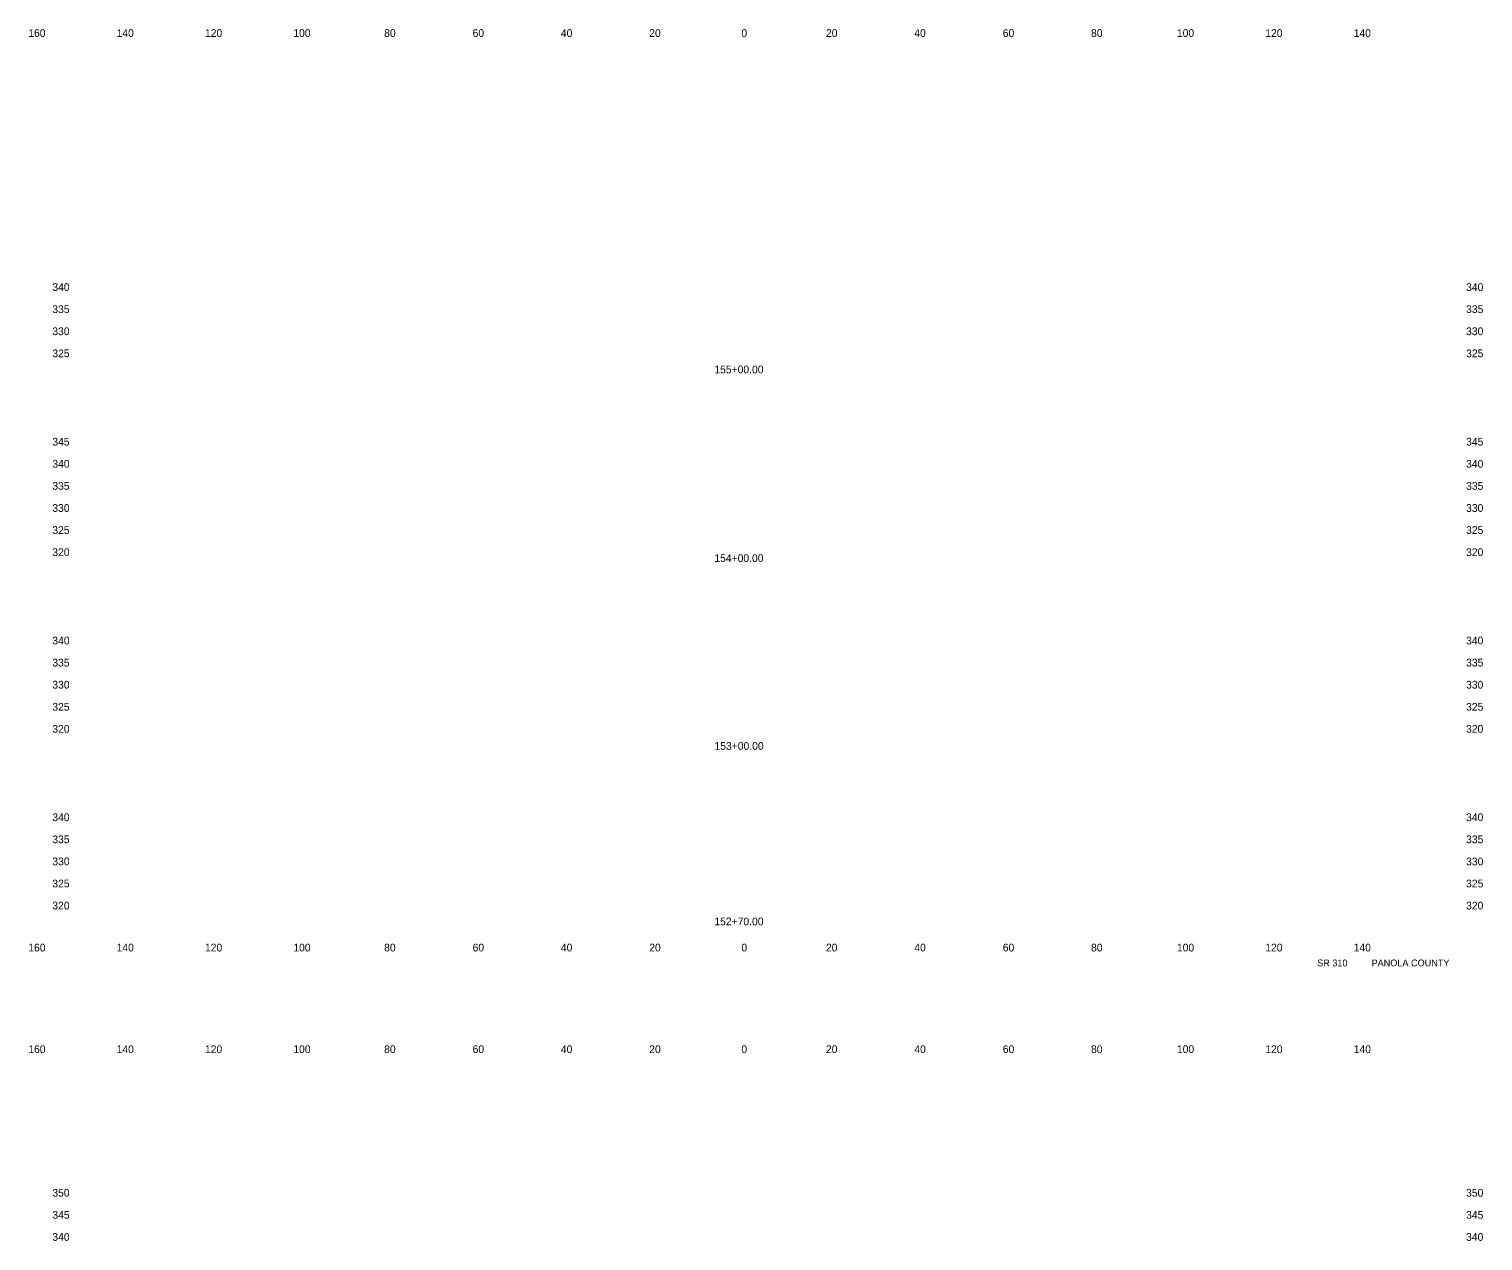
# Model space of a CAD drawing. Extents: x 21481 to 21810, y 6485 to 11067.
# Drawn here: x 21480.9 to 21809.9, y 10792.7 to 11067 of the extents above; entities that cross this region are included whole.
import ezdxf

# ---------------------------------------------------------------- set-up
doc = ezdxf.new("R2010")
doc.units = 0
for name, color, linetype in [('62', 7, 'Continuous'), ('XS_CELL', 7, 'Continuous'), ('XS_P_TX_DCH', 7, 'Continuous'), ('XS_P_TX_FS_BS', 7, 'Continuous')]:
    doc.layers.add(name, color=color, linetype=linetype)

msp = doc.modelspace()

# ---------------------------------------------------------------- texts
at = {"layer": '62'}
for s, p in [('  160  ', (21479.4, 11065.21)), ('  140  ', (21499.39, 11065.21)), ('  120  ', (21519.39, 11065.21)), ('  100  ', (21539.39, 11065.21)), ('  80  ', (21559.95, 11065.21)), ('  60  ', (21579.97, 11065.21)), ('  40  ', (21599.95, 11065.21)), ('  20  ', (21619.95, 11065.21)), ('  0  ', (21640.81, 11065.21)), ('  0  ', (21640.81, 11065.21)), ('  20  ', (21659.95, 11065.21)), ('  40  ', (21679.95, 11065.21)), ('  60  ', (21699.97, 11065.21)), ('  80  ', (21719.95, 11065.21)), ('  100  ', (21739.39, 11065.21)), ('  120  ', (21759.39, 11065.21)), ('  140  ', (21779.39, 11065.21)), ('  160  ', (21479.4, 10858.21)), ('  140  ', (21499.39, 10858.21)), ('  120  ', (21519.39, 10858.21)), ('  100  ', (21539.39, 10858.21)), ('  80  ', (21559.95, 10858.21)), ('  60  ', (21579.97, 10858.21)), ('  40  ', (21599.95, 10858.21)), ('  20  ', (21619.95, 10858.21)), ('  0  ', (21640.81, 10858.21)), ('  0  ', (21640.81, 10858.21)), ('  20  ', (21659.95, 10858.21)), ('  40  ', (21679.95, 10858.21)), ('  60  ', (21699.97, 10858.21)), ('  80  ', (21719.95, 10858.21)), ('  100  ', (21739.39, 10858.21)), ('  120  ', (21759.39, 10858.21)), ('  140  ', (21779.39, 10858.21)), ('  160  ', (21479.4, 10835.21)), ('  140  ', (21499.39, 10835.21)), ('  120  ', (21519.39, 10835.21)), ('  100  ', (21539.39, 10835.21)), ('  80  ', (21559.95, 10835.21)), ('  60  ', (21579.97, 10835.21)), ('  40  ', (21599.95, 10835.21)), ('  20  ', (21619.95, 10835.21)), ('  0  ', (21640.81, 10835.21)), ('  0  ', (21640.81, 10835.21)), ('  20  ', (21659.95, 10835.21)), ('  40  ', (21679.95, 10835.21)), ('  60  ', (21699.97, 10835.21)), ('  80  ', (21719.95, 10835.21)), ('  100  ', (21739.39, 10835.21)), ('  120  ', (21759.39, 10835.21)), ('  140  ', (21779.39, 10835.21))]:
    msp.add_text(s, height=1.75, dxfattribs=at).set_placement(p)
at = {"layer": 'XS_CELL'}
for s, p in [('  340  ', (21484.84, 11007.71)), ('  340  ', (21804.84, 11007.71)), ('  335  ', (21484.84, 11002.71)), ('  335  ', (21804.84, 11002.71)), ('  330  ', (21484.84, 10997.71)), ('  330  ', (21804.84, 10997.71)), ('  325  ', (21484.84, 10992.71)), ('  325  ', (21804.84, 10992.71)), ('  345  ', (21484.84, 10972.71)), ('  345  ', (21804.84, 10972.71)), ('  340  ', (21484.84, 10967.71)), ('  340  ', (21804.84, 10967.71)), ('  335  ', (21484.84, 10962.71)), ('  335  ', (21804.84, 10962.71)), ('  330  ', (21484.84, 10957.71)), ('  330  ', (21804.84, 10957.71)), ('  325  ', (21484.84, 10952.71)), ('  325  ', (21804.84, 10952.71)), ('  320  ', (21484.84, 10947.71)), ('  320  ', (21804.84, 10947.71)), ('  340  ', (21484.84, 10927.71)), ('  340  ', (21804.84, 10927.71)), ('  335  ', (21484.84, 10922.71)), ('  335  ', (21804.84, 10922.71)), ('  330  ', (21484.84, 10917.71)), ('  330  ', (21804.84, 10917.71)), ('  325  ', (21484.84, 10912.71)), ('  325  ', (21804.84, 10912.71)), ('  320  ', (21484.84, 10907.71)), ('  320  ', (21804.84, 10907.71)), ('  340  ', (21484.84, 10887.71)), ('  340  ', (21804.84, 10887.71)), ('  335  ', (21484.84, 10882.71)), ('  335  ', (21804.84, 10882.71)), ('  330  ', (21484.84, 10877.71)), ('  330  ', (21804.84, 10877.71)), ('  325  ', (21484.84, 10872.71)), ('  325  ', (21804.84, 10872.71)), ('  320  ', (21484.84, 10867.71)), ('  320  ', (21804.84, 10867.71)), ('  350  ', (21484.84, 10802.71)), ('  350  ', (21804.84, 10802.71)), ('  345  ', (21484.84, 10797.71)), ('  345  ', (21804.84, 10797.71)), ('  340  ', (21484.84, 10792.71)), ('  340  ', (21804.84, 10792.71))]:
    msp.add_text(s, height=1.75, dxfattribs=at).set_placement(p)
at = {"layer": 'XS_P_TX_DCH'}
for s, p in [('  155+00.00  ', (21634.69, 10989.06)), ('  154+00.00  ', (21634.69, 10946.36)), ('  153+00.00  ', (21634.72, 10903.85)), ('  152+70.00  ', (21634.69, 10864.12))]:
    msp.add_text(s, height=1.75, dxfattribs=at).set_placement(p)
at = {"layer": 'XS_P_TX_FS_BS'}
for s, p in [('SR 310', (21772.43, 10854.84)), ('PANOLA COUNTY', (21784.75, 10854.84))]:
    msp.add_text(s, height=1.54, dxfattribs=at).set_placement(p)

doc.saveas('drawing.dxf')
